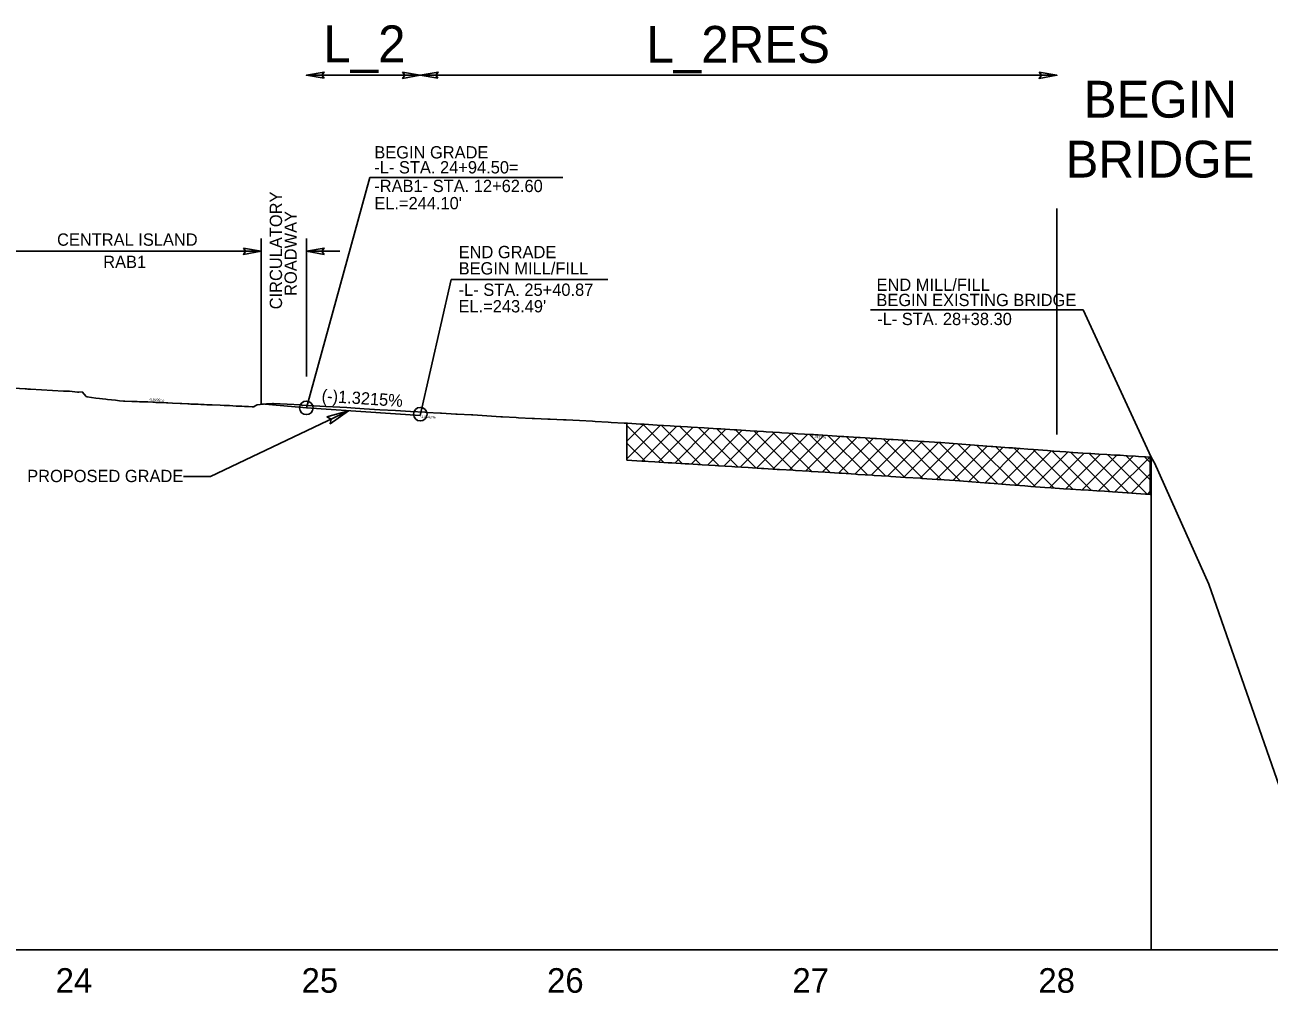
# Model space of a CAD drawing. Extents: x 2115752 to 2121174, y 562881 to 567245.
# Drawn here: x 2118076 to 2118583, y 566358 to 566752 of the extents above; entities that cross this region are included whole.
import ezdxf

# ---------------------------------------------------------------- set-up
doc = ezdxf.new("R2010")
doc.units = 0
for name, color, linetype in [('Exist Profile Cell', 7, 'Continuous'), ('Exist Vertical Profile Ground Line', 7, 'Continuous'), ('Exist Vertical Profile Horizontal Axis Label Major', 7, 'Continuous'), ('Prop Terminator CELL', 7, 'Continuous'), ('Prop Vertical Profile Grade', 7, 'Continuous'), ('Prop Vertical Profile Grade Label', 7, 'Continuous'), ('Prop VPI Label', 7, 'Continuous'), ('Prop XS Undercut Exc', 7, 'Continuous'), ('Prop XS Undercut Exc Hatch', 7, 'Continuous'), ('Scratch_Level_1', 7, 'Continuous')]:
    doc.layers.add(name, color=color, linetype=linetype)

msp = doc.modelspace()

# ---------------------------------------------------------------- linework, layer by layer
at = {"layer": 'Exist Profile Cell'}
msp.add_line((2116696.3, 566375.81), (2121174.42, 566375.81), dxfattribs=at)
at = {"layer": 'Exist Vertical Profile Ground Line'}
for points in [[(2118064.82, 566604.69), (2118076.37, 566604.03), (2118076.91, 566604.01), (2118077.47, 566603.99), (2118078, 566603.96), (2118078.51, 566603.92), (2118091.96, 566603.16), (2118092.38, 566603.13), (2118092.83, 566603.11), (2118093.46, 566603.09), (2118094.32, 566603.06), (2118097.65, 566602.77), (2118098.24, 566602.77), (2118099.5, 566602.85), (2118100.31, 566601.87), (2118101.2, 566600.97), (2118101.54, 566600.85), (2118103.37, 566600.56), (2118105.16, 566600.33), (2118106.63, 566600.1), (2118107.81, 566599.94), (2118109.18, 566599.81), (2118109.9, 566599.72), (2118113.14, 566599.46), (2118114.78, 566599.21), (2118116.39, 566599.12), (2118116.87, 566599.09), (2118119.69, 566598.97), (2118120.67, 566598.93), (2118121.91, 566598.89), (2118122.91, 566598.85), (2118124.6, 566598.8), (2118126.28, 566598.74), (2118128.3, 566598.63), (2118128.95, 566598.59), (2118129.54, 566598.57), (2118132.34, 566598.51), (2118132.77, 566598.49), (2118134.35, 566598.35), (2118136.25, 566598.27), (2118139.4, 566598.13), (2118140.09, 566598.09), (2118142.58, 566597.94), (2118143.08, 566597.91), (2118143.71, 566597.9), (2118144.95, 566597.86), (2118145.88, 566597.82), (2118146.8, 566597.77), (2118147.8, 566597.74), (2118149.25, 566597.68), (2118150.28, 566597.61), (2118151.71, 566597.56), (2118152.17, 566597.53), (2118152.5, 566597.52), (2118155.76, 566597.41), (2118157.36, 566597.36), (2118159.01, 566597.27), (2118159.53, 566597.24), (2118162.26, 566597.07), (2118162.63, 566597.03), (2118163.1, 566597.03), (2118164.47, 566596.96), (2118165.57, 566596.93), (2118167.21, 566596.86), (2118168.71, 566596.78), (2118169.42, 566596.74), (2118169.97, 566597.1), (2118170.75, 566597.57), (2118174.61, 566597.91), (2118175.93, 566598.02), (2118177.06, 566598.07), (2118177.4, 566598.08), (2118188.57, 566597.5), (2118188.89, 566597.48), (2118198.76, 566596.93), (2118207.26, 566596.43), (2118208.94, 566596.33), (2118214.3, 566595.99), (2118220.66, 566595.59), (2118227.06, 566595.2), (2118233.14, 566594.85), (2118239.06, 566594.53), (2118239.5, 566594.51), (2118245.36, 566594.19), (2118245.85, 566594.17), (2118251.65, 566593.83), (2118252.2, 566593.81)], [(2118252.2, 566593.81), (2118257.95, 566593.46), (2118258.6, 566593.43), (2118264.3, 566593.07), (2118269.89, 566592.72), (2118270.69, 566592.68), (2118276.24, 566592.37), (2118277.15, 566592.31), (2118282.65, 566592.04), (2118283.62, 566591.98), (2118289.09, 566591.75), (2118290.1, 566591.69), (2118295.52, 566591.45), (2118296.55, 566591.4), (2118301.95, 566591.14), (2118307.29, 566590.85), (2118308.36, 566590.81), (2118313.69, 566590.49), (2118314.84, 566590.44), (2118320.16, 566590.11), (2118321.48, 566590.05), (2118326.8, 566589.72), (2118328.27, 566589.64), (2118333.59, 566589.31), (2118338.94, 566588.99), (2118340.51, 566588.9), (2118345.87, 566588.57), (2118347.39, 566588.48), (2118352.76, 566588.15), (2118358.16, 566587.82), (2118359.49, 566587.74), (2118364.9, 566587.41), (2118366.08, 566587.34), (2118371.49, 566587.01), (2118376.93, 566586.68), (2118377.96, 566586.61), (2118383.41, 566586.28), (2118384.37, 566586.22), (2118389.84, 566585.89), (2118390.79, 566585.83), (2118396.33, 566585.49), (2118397.26, 566585.43), (2118402.89, 566585.08), (2118408.66, 566584.72), (2118409.52, 566584.67), (2118415.4, 566584.3), (2118416.21, 566584.25), (2118422.16, 566583.87), (2118422.91, 566583.82), (2118428.9, 566583.45), (2118429.59, 566583.4), (2118435.62, 566583.02), (2118441.73, 566582.64), (2118442.33, 566582.6), (2118448.57, 566582.2), (2118449.07, 566582.17), (2118455.87, 566581.7), (2118462.73, 566581.21), (2118469.5, 566580.67), (2118470.16, 566580.63), (2118476.69, 566580.12), (2118478.24, 566580), (2118484.43, 566579.53), (2118486.76, 566579.35), (2118492.42, 566578.92), (2118494.99, 566578.75), (2118499.97, 566578.38), (2118502.73, 566578.22), (2118506.91, 566577.94), (2118510.1, 566577.75), (2118513.4, 566577.55), (2118516.66, 566577.35), (2118519.78, 566577.13), (2118522.04, 566577.02), (2118524.95, 566576.81), (2118528.31, 566576.63), (2118529.48, 566576.58), (2118532.4, 566576.42), (2118534.61, 566576.28), (2118535.71, 566574.35), (2118536.01, 566573.91), (2118547.05, 566549.35), (2118558.09, 566524.65), (2118590.94, 566430.42)]]:
    msp.add_lwpolyline(points, dxfattribs=at)
at = {"layer": 'Prop Terminator CELL'}
for points in [[(2118165.21, 566661.29), (2118172.41, 566660.05), (2118165.17, 566658.77), (2118166.09, 566660.05)], [(2118198, 566658.81), (2118190.8, 566660.05), (2118198.04, 566661.33), (2118197.12, 566660.05)], [(2118199.17, 566592.7), (2118207.96, 566595.19), (2118200.49, 566589.84), (2118200.83, 566591.78)]]:
    msp.add_lwpolyline(points, close=True, dxfattribs=at)
at = {"layer": 'Prop Vertical Profile Grade'}
msp.add_line((2118190.8, 566596.32), (2118237.17, 566593.26), dxfattribs=at)
at = {"layer": 'Prop VPI Label'}
for p, q in [((2118190.8, 566596.32), (2118216.68, 566690.13)), ((2118216.68, 566690.13), (2118295.23, 566690.13)), ((2118172.41, 566597.94), (2118172.41, 566665.25)), ((2118190.8, 566609.08), (2118190.8, 566665.25)), ((2118061.61, 566660.05), (2118172.41, 566660.05)), ((2118190.8, 566660.05), (2118204.38, 566660.05)), ((2118237.17, 566593.28), (2118249.7, 566648.59)), ((2118249.7, 566648.59), (2118313.45, 566648.59)), ((2118420.46, 566636.2), (2118507, 566636.2)), ((2118534.6, 566576.28), (2118507, 566636.2)), ((2118190.8, 566596.32), (2118172.41, 566597.94))]:
    msp.add_line(p, q, dxfattribs=at)
msp.add_lwpolyline([(2118140.72, 566568.36), (2118151.84, 566568.36), (2118207.96, 566595.19)], dxfattribs=at)
for centre in [(2118190.8, 566596.32), (2118237.17, 566593.76)]:
    msp.add_circle(centre, 2.75, dxfattribs=at)
at = {"layer": 'Prop XS Undercut Exc'}
for p, q in [((2118321.3, 566575.01), (2118321.3, 566590.06)), ((2118534.3, 566561.12), (2118534.3, 566576.3))]:
    msp.add_line(p, q, dxfattribs=at)
msp.add_lwpolyline([(2118321.3, 566575.01), (2118327.39, 566574.66), (2118332.68, 566574.34), (2118338.04, 566574.02), (2118339.6, 566573.92), (2118344.95, 566573.6), (2118346.47, 566573.5), (2118351.85, 566573.18), (2118357.24, 566572.85), (2118358.57, 566572.77), (2118363.97, 566572.44), (2118365.16, 566572.37), (2118370.58, 566572.04), (2118376.01, 566571.71), (2118377.03, 566571.64), (2118382.49, 566571.31), (2118383.44, 566571.25), (2118388.91, 566570.92), (2118389.86, 566570.86), (2118395.39, 566570.52), (2118396.33, 566570.46), (2118401.96, 566570.11), (2118407.72, 566569.75), (2118408.58, 566569.7), (2118414.45, 566569.33), (2118415.26, 566569.28), (2118421.21, 566568.9), (2118421.96, 566568.85), (2118427.95, 566568.48), (2118428.64, 566568.43), (2118434.68, 566568.05), (2118440.78, 566567.67), (2118441.37, 566567.63), (2118447.6, 566567.23), (2118448.07, 566567.2), (2118454.82, 566566.74), (2118461.6, 566566.25), (2118468.42, 566565.71), (2118469.08, 566565.67), (2118475.54, 566565.16), (2118477.1, 566565.04), (2118483.28, 566564.57), (2118485.62, 566564.39), (2118491.35, 566563.96), (2118493.93, 566563.79), (2118498.98, 566563.42), (2118501.77, 566563.25), (2118505.97, 566562.97), (2118509.22, 566562.77), (2118512.5, 566562.58), (2118515.67, 566562.39), (2118518.87, 566562.16), (2118521.13, 566562.05), (2118534.3, 566561.12)], dxfattribs=at)
at = {"layer": 'Prop XS Undercut Exc Hatch'}
for p, q in [((2118321.3, 566589.8), (2118321.55, 566590.04)), ((2118321.3, 566582.72), (2118328.22, 566589.64)), ((2118321.3, 566575.65), (2118334.89, 566589.24)), ((2118321.3, 566589.1), (2118336.28, 566574.12)), ((2118327.39, 566574.66), (2118341.55, 566588.83)), ((2118327.81, 566589.66), (2118343.8, 566573.67)), ((2118334.05, 566574.26), (2118348.22, 566588.43)), ((2118335.33, 566589.21), (2118351.33, 566573.21)), ((2118340.72, 566573.86), (2118354.89, 566588.02)), ((2118342.86, 566588.75), (2118358.86, 566572.75)), ((2118347.38, 566573.45), (2118361.55, 566587.62)), ((2118350.39, 566588.3), (2118366.39, 566572.29)), ((2118354.05, 566573.05), (2118368.22, 566587.21)), ((2118357.92, 566587.84), (2118373.92, 566571.83)), ((2118360.72, 566572.64), (2118374.88, 566586.8)), ((2118365.45, 566587.38), (2118381.45, 566571.37)), ((2118367.38, 566572.23), (2118381.54, 566586.4)), ((2118372.98, 566586.92), (2118388.99, 566570.91)), ((2118374.05, 566571.83), (2118388.21, 566585.99)), ((2118380.51, 566586.46), (2118396.52, 566570.44)), ((2118388.04, 566586), (2118404.06, 566569.98)), ((2118321.3, 566582.02), (2118328.75, 566574.58)), ((2118380.71, 566571.42), (2118394.87, 566585.58)), ((2118387.37, 566571.01), (2118401.53, 566585.16)), ((2118394.03, 566570.6), (2118408.18, 566584.75)), ((2118395.58, 566585.53), (2118411.6, 566569.51)), ((2118400.69, 566570.19), (2118414.84, 566584.33)), ((2118403.12, 566585.07), (2118419.15, 566569.03)), ((2118407.35, 566569.77), (2118421.49, 566583.91)), ((2118410.66, 566584.59), (2118426.7, 566568.56)), ((2118414, 566569.36), (2118428.14, 566583.5)), ((2118418.2, 566584.12), (2118434.24, 566568.08)), ((2118420.65, 566568.94), (2118434.79, 566583.08)), ((2118425.75, 566583.65), (2118441.79, 566567.61)), ((2118427.31, 566568.52), (2118441.45, 566582.66)), ((2118433.29, 566583.17), (2118449.35, 566567.11)), ((2118433.96, 566568.1), (2118448.09, 566582.23)), ((2118440.61, 566567.68), (2118454.71, 566581.78)), ((2118440.84, 566582.7), (2118456.95, 566566.58)), ((2118447.25, 566567.25), (2118461.31, 566581.31)), ((2118448.4, 566582.21), (2118464.59, 566566.01)), ((2118453.87, 566566.8), (2118467.87, 566580.8)), ((2118455.99, 566581.69), (2118472.26, 566565.42)), ((2118463.61, 566581.14), (2118479.92, 566564.83)), ((2118460.47, 566566.33), (2118474.44, 566580.3)), ((2118467.04, 566565.82), (2118481, 566579.79)), ((2118471.28, 566580.54), (2118487.58, 566564.25)), ((2118473.6, 566565.31), (2118487.57, 566579.29)), ((2118478.94, 566579.95), (2118495.2, 566563.69)), ((2118480.17, 566564.81), (2118494.16, 566578.81)), ((2118486.6, 566579.36), (2118502.78, 566563.18)), ((2118486.74, 566564.31), (2118500.76, 566578.34)), ((2118493.33, 566563.83), (2118507.4, 566577.91)), ((2118494.23, 566578.8), (2118510.32, 566562.71)), ((2118499.93, 566563.36), (2118514.08, 566577.51)), ((2118501.83, 566578.27), (2118517.87, 566562.23)), ((2118506.57, 566562.93), (2118520.73, 566577.09)), ((2118509.39, 566577.79), (2118525.43, 566561.74)), ((2118513.25, 566562.53), (2118527.39, 566576.68)), ((2118516.91, 566577.34), (2118533.04, 566561.21)), ((2118519.89, 566562.11), (2118534.09, 566576.31)), ((2118524.47, 566576.85), (2118534.3, 566567.01)), ((2118531.94, 566576.45), (2118534.3, 566574.09)), ((2118526.52, 566561.67), (2118534.3, 566569.45)), ((2118533.13, 566561.2), (2118534.3, 566562.38))]:
    msp.add_line(p, q, dxfattribs=at)
at = {"layer": 'Scratch_Level_1'}
for p, q in [((2118190.8, 566731.71), (2118237.17, 566731.71)), ((2118237.17, 566731.71), (2118496.3, 566731.71)), ((2118496.3, 566585.49), (2118496.3, 566677.4)), ((2118126.28, 566598.74), (2118136.25, 566598.27)), ((2118396.3, 566585.49), (2118397.26, 566585.43)), ((2118396.33, 566585.49), (2118402.89, 566585.08)), ((2118534.6, 566375.81), (2118534.6, 566576.28))]:
    msp.add_line(p, q, dxfattribs=at)
for points in [[(2118198, 566730.47), (2118190.8, 566731.71), (2118198.04, 566732.99), (2118197.12, 566731.71)], [(2118229.97, 566732.95), (2118237.17, 566731.71), (2118229.93, 566730.43), (2118230.85, 566731.71)], [(2118244.37, 566730.47), (2118237.17, 566731.71), (2118244.41, 566732.99), (2118243.49, 566731.71)], [(2118489.1, 566732.95), (2118496.3, 566731.71), (2118489.06, 566730.43), (2118489.98, 566731.71)]]:
    msp.add_lwpolyline(points, close=True, dxfattribs=at)

# ---------------------------------------------------------------- texts
at = {"layer": 'Exist Vertical Profile Horizontal Axis Label Major'}
for s, p in [('24', (2118088.76, 566358.31)), ('25', (2118188.85, 566358.31)), ('26', (2118288.79, 566358.31)), ('27', (2118388.65, 566358.31)), ('28', (2118488.77, 566358.31))]:
    msp.add_text(s, height=10, dxfattribs=at).set_placement(p)
at = {"layer": 'Prop Vertical Profile Grade Label'}
msp.add_text('(-)1.3215%', height=5, rotation=356.2528, dxfattribs=at).set_placement((2118196.89, 566598.85))
at = {"layer": 'Prop VPI Label'}
for s, p in [('BEGIN GRADE', (2118218.45, 566697.83)), ('-L- STA. 24+94.50=', (2118218.45, 566691.73)), ('-RAB1- STA. 12+62.60', (2118218.45, 566684.15)), ("EL.=244.10'", (2118218.45, 566677.15)), ('CENTRAL ISLAND', (2118089.32, 566662.31)), ('END GRADE', (2118252.78, 566657.24)), ('RAB1', (2118108.11, 566653.25)), ('BEGIN MILL/FILL', (2118252.78, 566650.61)), ('-L- STA. 25+40.87', (2118252.78, 566641.92)), ('END MILL/FILL', (2118422.89, 566643.95)), ('BEGIN EXISTING BRIDGE', (2118422.83, 566637.74)), ("EL.=243.49'", (2118252.72, 566635.18)), ('-L- STA. 28+38.30', (2118423.13, 566630.02)), ('PROPOSED GRADE', (2118077.17, 566566.12))]:
    msp.add_text(s, height=5, dxfattribs=at).set_placement(p)
for s, p in [('CIRCULATORY', (2118180.9, 566636.44)), ('ROADWAY', (2118186.91, 566641.91))]:
    msp.add_text(s, height=5, rotation=90, dxfattribs=at).set_placement(p)
at = {"layer": 'Scratch_Level_1'}
for s, p in [('L_2', (2118197.69, 566736.96)), ('L_2RES', (2118329.21, 566736.75)), ('BEGIN', (2118507.2, 566714.43)), ('BRIDGE', (2118499.81, 566690.05))]:
    msp.add_text(s, height=15, dxfattribs=at).set_placement(p)
for s, rotation, p in [('-0.9299 %', 357.338, (2118126.67, 566599.24)), ('-1.0543 %', 356.9825, (2118237.05, 566592.3)), ('-1.2412 %', 356.4489, (2118396.07, 566584.14))]:
    msp.add_text(s, height=1, rotation=rotation, dxfattribs=at).set_placement(p)

doc.saveas('drawing.dxf')
